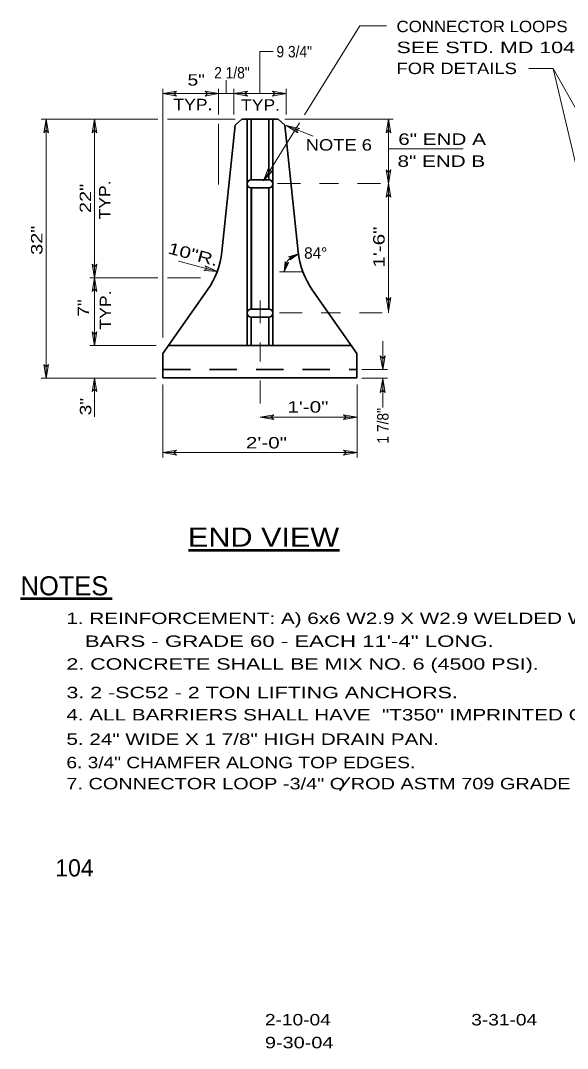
# Model space of a CAD drawing. Extents: x 12.4 to 19.4, y 5.8 to 15.9.
# Drawn here: x 12.38 to 15.25, y 6.26 to 11.65 of the extents above; entities that cross this region are included whole.
import ezdxf
from ezdxf.enums import TextEntityAlignment as Align

# ---------------------------------------------------------------- set-up
doc = ezdxf.new("R2010")
doc.units = 0
doc.header["$LTSCALE"] = 0.024
doc.linetypes.add('DOT_DASHED', pattern=[7.7, 5, -1.2, 0.3, -1.2])
doc.linetypes.add('LONG_DASHED', pattern=[7.5, 6, -1.5])
for name, color, linetype, lineweight in [('1', 7, 'Continuous', 35), ('10', 7, 'Continuous', 13), ('12', 7, 'Continuous', 53), ('13', 7, 'Continuous', 25)]:
    doc.layers.add(name, color=color, linetype=linetype, lineweight=lineweight)

msp = doc.modelspace()

# ---------------------------------------------------------------- hatches: boundary and pattern name
at = {"layer": '10'}
for points in [[(13.1978, 11.2574), (13.1263, 11.27), (13.1978, 11.2826), (13.1843, 11.27)], [(13.3483, 11.2826), (13.4198, 11.27), (13.3483, 11.2574), (13.3618, 11.27)], [(13.5709, 11.2574), (13.4994, 11.27), (13.5709, 11.2826), (13.5574, 11.27)], [(13.7016, 11.2826), (13.7731, 11.27), (13.7016, 11.2574), (13.7151, 11.27)], [(12.5018, 11.0646), (12.5144, 11.1361), (12.527, 11.0646), (12.5144, 11.0781)], [(12.7555, 11.0646), (12.7681, 11.1361), (12.7807, 11.0646), (12.7681, 11.0781)], [(14.2978, 11.0646), (14.3104, 11.1361), (14.323, 11.0646), (14.3104, 11.0781)], [(13.8354, 11.0641), (13.7735, 11.102), (13.8446, 11.0876), (13.8275, 11.0808)], [(13.7032, 10.8665), (13.6547, 10.8125), (13.6818, 10.8799), (13.6853, 10.8617)], [(14.323, 10.8705), (14.3104, 10.799), (14.2978, 10.8705), (14.3104, 10.857)], [(14.2978, 10.7275), (14.3104, 10.799), (14.323, 10.7275), (14.3104, 10.741)], [(13.7861, 10.414), (13.838, 10.4299), (13.7946, 10.3974), (13.7992, 10.4103)], [(12.7807, 10.3749), (12.7681, 10.3034), (12.7555, 10.3749), (12.7681, 10.3614)], [(13.3483, 10.367), (13.4141, 10.3364), (13.3418, 10.3426), (13.3581, 10.3513)], [(13.7873, 10.3848), (13.7641, 10.3355), (13.7691, 10.3898), (13.7757, 10.3773)], [(12.7555, 10.2319), (12.7681, 10.3034), (12.7807, 10.2319), (12.7681, 10.2454)], [(14.323, 10.1997), (14.3104, 10.1282), (14.2978, 10.1997), (14.3104, 10.1862)], [(12.7807, 10.0204), (12.7681, 9.9489), (12.7555, 10.0204), (12.7681, 10.0069)], [(14.2931, 9.894), (14.2805, 9.8225), (14.2679, 9.894), (14.2805, 9.8805)], [(12.527, 9.8494), (12.5144, 9.7779), (12.5018, 9.8494), (12.5144, 9.8359)], [(12.7555, 9.7064), (12.7681, 9.7779), (12.7807, 9.7064), (12.7681, 9.7199)], [(14.2679, 9.7015), (14.2805, 9.773), (14.2931, 9.7015), (14.2805, 9.715)], [(13.7089, 9.5596), (13.6374, 9.5722), (13.7089, 9.5848), (13.6954, 9.5722)], [(14.0747, 9.5848), (14.1462, 9.5722), (14.0747, 9.5596), (14.0882, 9.5722)], [(13.1978, 9.3737), (13.1263, 9.3863), (13.1978, 9.3989), (13.1843, 9.3863)], [(14.0747, 9.3989), (14.1462, 9.3863), (14.0747, 9.3737), (14.0882, 9.3863)]]:
    msp.add_hatch(color=256, dxfattribs=at).paths.add_polyline_path(points)

# ---------------------------------------------------------------- linework, layer by layer
at = {"layer": '1'}
for p, q in [((13.5059, 11.1044), (13.541, 11.1362)), ((13.541, 11.1362), (13.7318, 11.1362)), ((13.569, 11.1357), (13.569, 9.9515)), ((13.5902, 11.1357), (13.5902, 10.8178)), ((13.6832, 11.1357), (13.6832, 10.8178)), ((13.7041, 11.1357), (13.7041, 9.9515)), ((13.7669, 11.1044), (13.7318, 11.1362)), ((13.436, 10.4396), (13.5059, 11.1044)), ((13.8369, 10.4396), (13.7669, 11.1044)), ((13.6832, 10.8178), (13.5902, 10.8178)), ((13.6832, 10.7754), (13.5902, 10.7754)), ((13.6832, 10.7754), (13.6832, 10.1395)), ((13.3616, 10.2409), (13.1277, 9.9068)), ((13.9112, 10.2409), (14.1452, 9.9068)), ((13.6832, 10.1395), (13.5902, 10.1395)), ((13.5902, 9.9515), (13.5902, 10.097)), ((13.6832, 10.097), (13.5902, 10.097)), ((13.6832, 9.9515), (13.6832, 10.097)), ((13.1573, 9.9492), (14.1154, 9.9492)), ((13.1277, 9.7795), (13.1277, 9.9068)), ((14.1452, 9.7795), (14.1452, 9.9068)), ((13.1277, 9.7795), (14.1452, 9.7795))]:
    msp.add_line(p, q, dxfattribs=at)
at = {"layer": '1', "lineweight": 40}
msp.add_line((13.5902, 10.7754), (13.5902, 10.1395), dxfattribs=at)
at = {"layer": '1', "linetype": 'LONG_DASHED'}
msp.add_line((13.1277, 9.8219), (14.1452, 9.8219), dxfattribs=at)
at = {"layer": '1'}
for centre, radius, start, end in [((13.59027, 10.79654), 0.0212, 90.6627, 269.33729), ((13.68293, 10.79654), 0.0212, 270.64822, 89.35178), ((13.0143, 10.48399), 0.42393, 325.00891, 353.98557), ((14.2585, 10.48398), 0.42393, 186.00677, 214.99444), ((13.59027, 10.11825), 0.0212, 90.6627, 269.33729), ((13.68293, 10.11825), 0.0212, 270.64822, 89.35178)]:
    msp.add_arc(centre, radius, start, end, dxfattribs=at)
at = {"layer": '10'}
for p, q in [((14.1612, 11.6264), (13.8708, 11.1596)), ((14.3002, 11.6264), (14.1612, 11.6264)), ((15.1742, 11.4026), (15.471, 10.1432)), ((13.4596, 11.27), (13.4596, 11.3403)), ((13.1263, 9.9911), (13.1263, 11.295)), ((13.1263, 11.27), (13.1978, 11.2826)), ((13.4198, 11.27), (13.3483, 11.2826)), ((13.4198, 11.295), (13.4198, 11.1611)), ((13.4994, 11.1611), (13.4994, 11.295)), ((13.4994, 11.27), (13.5709, 11.2826)), ((13.7731, 11.27), (13.7016, 11.2826)), ((13.7731, 11.1611), (13.7731, 11.295)), ((13.1263, 11.27), (13.1978, 11.2574)), ((13.4198, 11.27), (13.3483, 11.2574)), ((13.4994, 11.27), (13.5709, 11.2574)), ((13.7731, 11.27), (13.7016, 11.2574)), ((12.4894, 11.1361), (13.1013, 11.1361)), ((12.5144, 11.1361), (12.5018, 11.0646)), ((12.5144, 11.1361), (12.5144, 9.7779)), ((12.5144, 11.1361), (12.527, 11.0646)), ((12.7681, 11.1361), (12.7555, 11.0646)), ((12.7681, 11.1361), (12.7681, 10.3034)), ((12.7681, 11.1361), (12.7807, 11.0646)), ((13.506, 11.1361), (13.1513, 11.1361)), ((13.4198, 10.7941), (13.4198, 11.1111)), ((13.6547, 10.8125), (13.8442, 11.1169)), ((13.7668, 11.1361), (14.3354, 11.1361)), ((14.3104, 11.1361), (14.2978, 11.0646)), ((14.3104, 11.1361), (14.323, 11.0646)), ((13.7735, 11.102), (13.9162, 11.0466)), ((13.7735, 11.102), (13.8354, 11.0641)), ((13.7735, 11.102), (13.8446, 11.0876)), ((14.3105, 10.9799), (14.7033, 10.9799)), ((13.6547, 10.8125), (13.6818, 10.8799)), ((13.6547, 10.8125), (13.7032, 10.8665)), ((14.3104, 10.799), (14.2978, 10.8705)), ((14.3104, 10.799), (14.323, 10.8705)), ((14.3104, 10.799), (14.2978, 10.7275)), ((14.3104, 10.799), (14.323, 10.7275)), ((13.838, 10.4299), (13.7861, 10.414)), ((13.838, 10.4299), (13.7946, 10.3974)), ((12.7681, 10.3034), (12.7555, 10.3749)), ((12.7681, 10.3034), (12.7807, 10.3749)), ((13.4141, 10.3364), (13.2099, 10.3908)), ((13.4141, 10.3364), (13.3483, 10.367)), ((13.7641, 10.3355), (13.7691, 10.3898)), ((13.7641, 10.3355), (13.7873, 10.3848)), ((12.7431, 10.3034), (13.1013, 10.3034)), ((12.7681, 10.3034), (12.7555, 10.2319)), ((12.7681, 10.3034), (12.7807, 10.2319)), ((12.7681, 10.3034), (12.7681, 9.9489)), ((13.3253, 10.3034), (13.1513, 10.3034)), ((13.4141, 10.3364), (13.3418, 10.3426)), ((13.8614, 10.3355), (13.7391, 10.3355)), ((14.3104, 10.1282), (14.2978, 10.1997)), ((14.3104, 10.1282), (14.323, 10.1997)), ((12.7681, 9.9489), (12.7555, 10.0204)), ((12.7681, 9.9489), (12.7807, 10.0204)), ((13.0927, 9.9489), (12.7431, 9.9489)), ((14.2805, 9.8225), (14.2805, 9.9716)), ((14.2805, 9.8225), (14.2679, 9.894)), ((14.2805, 9.8225), (14.2931, 9.894)), ((12.5144, 9.7779), (12.5018, 9.8494)), ((12.5144, 9.7779), (12.527, 9.8494)), ((14.1711, 9.8225), (14.3055, 9.8225)), ((13.0927, 9.7779), (12.4894, 9.7779)), ((12.7681, 9.7779), (12.7555, 9.7064)), ((12.7681, 9.7779), (12.7681, 9.5735)), ((12.7681, 9.7779), (12.7807, 9.7064)), ((14.1711, 9.7779), (14.3055, 9.7779)), ((14.2805, 9.773), (14.2679, 9.7015)), ((14.2805, 9.773), (14.2805, 9.6238)), ((14.2805, 9.773), (14.2931, 9.7015)), ((13.1263, 9.7445), (13.1263, 9.3613)), ((14.1462, 9.7445), (14.1462, 9.3613)), ((13.6374, 9.5722), (13.7089, 9.5848)), ((14.1462, 9.5722), (13.6374, 9.5722)), ((13.6374, 9.5722), (13.7089, 9.5596)), ((14.1462, 9.5722), (14.0747, 9.5848)), ((14.1462, 9.5722), (14.0747, 9.5596)), ((13.1263, 9.3863), (13.1978, 9.3989)), ((13.1263, 9.3863), (14.1462, 9.3863)), ((13.1263, 9.3863), (13.1978, 9.3737)), ((14.1462, 9.3863), (14.0747, 9.3989)), ((14.1462, 9.3863), (14.0747, 9.3737))]:
    msp.add_line(p, q, dxfattribs=at)
at = {"layer": '10', "linetype": 'DOT_DASHED'}
for p, q in [((13.7283, 10.799), (14.3354, 10.799)), ((13.6374, 10.1849), (13.6374, 9.5472)), ((13.7382, 10.1199), (14.3354, 10.1199))]:
    msp.add_line(p, q, dxfattribs=at)
at = {"layer": '10'}
for points in [[(13.6363, 11.27), (13.6363, 11.4919), (13.7066, 11.4919)], [(15.0476, 11.4026), (15.1742, 11.4026), (15.5051, 10.8165)], [(13.1978, 11.2574), (13.1843, 11.27), (13.1978, 11.2826)], [(13.3483, 11.2826), (13.3618, 11.27), (13.3483, 11.2574)], [(13.5709, 11.2574), (13.5574, 11.27), (13.5709, 11.2826)], [(13.7016, 11.2826), (13.7151, 11.27), (13.7016, 11.2574)], [(13.1263, 11.27), (13.4198, 11.27), (13.4994, 11.27), (13.7731, 11.27)], [(14.3104, 11.1361), (14.3104, 10.799), (14.3104, 10.1199)], [(12.5018, 11.0646), (12.5144, 11.0781), (12.527, 11.0646)], [(12.7555, 11.0646), (12.7681, 11.0781), (12.7807, 11.0646)], [(13.8354, 11.0641), (13.8275, 11.0808), (13.8446, 11.0876)], [(14.2978, 11.0646), (14.3104, 11.0781), (14.323, 11.0646)], [(13.7032, 10.8665), (13.6853, 10.8617), (13.6818, 10.8799)], [(14.323, 10.8705), (14.3104, 10.857), (14.2978, 10.8705)], [(14.2978, 10.7275), (14.3104, 10.741), (14.323, 10.7275)], [(13.7861, 10.414), (13.7992, 10.4103), (13.7946, 10.3974)], [(12.7807, 10.3749), (12.7681, 10.3614), (12.7555, 10.3749)], [(13.3483, 10.367), (13.3581, 10.3513), (13.3418, 10.3426)], [(13.7873, 10.3848), (13.7757, 10.3773), (13.7691, 10.3898)], [(12.7555, 10.2319), (12.7681, 10.2454), (12.7807, 10.2319)], [(14.323, 10.1997), (14.3104, 10.1862), (14.2978, 10.1997)], [(12.7807, 10.0204), (12.7681, 10.0069), (12.7555, 10.0204)], [(14.2931, 9.894), (14.2805, 9.8805), (14.2679, 9.894)], [(12.527, 9.8494), (12.5144, 9.8359), (12.5018, 9.8494)], [(12.7555, 9.7064), (12.7681, 9.7199), (12.7807, 9.7064)], [(14.2679, 9.7015), (14.2805, 9.715), (14.2931, 9.7015)], [(13.7089, 9.5596), (13.6954, 9.5722), (13.7089, 9.5848)], [(14.0747, 9.5848), (14.0882, 9.5722), (14.0747, 9.5596)], [(13.1978, 9.3737), (13.1843, 9.3863), (13.1978, 9.3989)], [(14.0747, 9.3989), (14.0882, 9.3863), (14.0747, 9.3737)]]:
    msp.add_lwpolyline(points, dxfattribs=at)
for points in [[(13.1978, 11.2574), (13.1263, 11.27), (13.1978, 11.2826), (13.1843, 11.27)], [(13.3483, 11.2826), (13.4198, 11.27), (13.3483, 11.2574), (13.3618, 11.27)], [(13.5709, 11.2574), (13.4994, 11.27), (13.5709, 11.2826), (13.5574, 11.27)], [(13.7016, 11.2826), (13.7731, 11.27), (13.7016, 11.2574), (13.7151, 11.27)], [(12.5018, 11.0646), (12.5144, 11.1361), (12.527, 11.0646), (12.5144, 11.0781)], [(12.7555, 11.0646), (12.7681, 11.1361), (12.7807, 11.0646), (12.7681, 11.0781)], [(14.2978, 11.0646), (14.3104, 11.1361), (14.323, 11.0646), (14.3104, 11.0781)], [(13.8354, 11.0641), (13.7735, 11.102), (13.8446, 11.0876), (13.8275, 11.0808)], [(13.7032, 10.8665), (13.6547, 10.8125), (13.6818, 10.8799), (13.6853, 10.8617)], [(14.323, 10.8705), (14.3104, 10.799), (14.2978, 10.8705), (14.3104, 10.857)], [(14.2978, 10.7275), (14.3104, 10.799), (14.323, 10.7275), (14.3104, 10.741)], [(13.7861, 10.414), (13.838, 10.4299), (13.7946, 10.3974), (13.7992, 10.4103)], [(12.7807, 10.3749), (12.7681, 10.3034), (12.7555, 10.3749), (12.7681, 10.3614)], [(13.3483, 10.367), (13.4141, 10.3364), (13.3418, 10.3426), (13.3581, 10.3513)], [(13.7873, 10.3848), (13.7641, 10.3355), (13.7691, 10.3898), (13.7757, 10.3773)], [(12.7555, 10.2319), (12.7681, 10.3034), (12.7807, 10.2319), (12.7681, 10.2454)], [(14.323, 10.1997), (14.3104, 10.1282), (14.2978, 10.1997), (14.3104, 10.1862)], [(12.7807, 10.0204), (12.7681, 9.9489), (12.7555, 10.0204), (12.7681, 10.0069)], [(14.2931, 9.894), (14.2805, 9.8225), (14.2679, 9.894), (14.2805, 9.8805)], [(12.527, 9.8494), (12.5144, 9.7779), (12.5018, 9.8494), (12.5144, 9.8359)], [(12.7555, 9.7064), (12.7681, 9.7779), (12.7807, 9.7064), (12.7681, 9.7199)], [(14.2679, 9.7015), (14.2805, 9.773), (14.2931, 9.7015), (14.2805, 9.715)], [(13.7089, 9.5596), (13.6374, 9.5722), (13.7089, 9.5848), (13.6954, 9.5722)], [(14.0747, 9.5848), (14.1462, 9.5722), (14.0747, 9.5596), (14.0882, 9.5722)], [(13.1978, 9.3737), (13.1263, 9.3863), (13.1978, 9.3989), (13.1843, 9.3863)], [(14.0747, 9.3989), (14.1462, 9.3863), (14.0747, 9.3737), (14.0882, 9.3863)]]:
    msp.add_lwpolyline(points, close=True, dxfattribs=at)
msp.add_arc((13.86144, 10.33551), 0.0973, 103.92901, 180, dxfattribs=at)
at = {"layer": '12'}
msp.add_line((13.2624, 8.8746), (14.0546, 8.8746), dxfattribs=at)
at = {"layer": '13', "lineweight": 53}
msp.add_line((12.3805, 8.6209), (12.8615, 8.6209), dxfattribs=at)
at = {"layer": '13'}
msp.add_line((14.1065, 7.6846), (14.0539, 7.6115), dxfattribs=at)

# ---------------------------------------------------------------- texts
at = {"layer": '12'}
for s, width, p in [('CONNECTOR LOOPS', 1.1, (14.353, 11.5925)), ('SEE STD. MD 104.01-54', 1.4, (14.353, 11.4825)), ('9 3/4"', 0.9, (13.7232, 11.4604)), ('FOR DETAILS', 1.2, (14.353, 11.3725)), ('2 1/8"', 0.9, (13.3964, 11.3496)), ('5"', 1.25, (13.2565, 11.3118)), ('TYP.', 1.15, (13.1821, 11.1828)), ('TYP.', 1.15, (13.5368, 11.1806)), ('6" END A', 1.35, (14.362, 11.0011)), ('NOTE 6', 1.2, (13.8763, 10.9711)), ('8" END B', 1.35, (14.3582, 10.8858)), ('1\'-0"', 1.35, (13.7802, 9.5963)), ('2\'-0"', 1.35, (13.5627, 9.4083))]:
    msp.add_text(s, height=0.06, dxfattribs=dict(at, width=width)).set_placement(p)
for s, rotation, width, p in [('22"', 90, 1.3, (12.7506, 10.6438)), ('TYP.', 90, 1.15, (12.8522, 10.6098)), ('32"', 90, 1.3, (12.4953, 10.4241)), ('1\'-6"', 90, 1.35, (14.2905, 10.357)), ('10"R.', 345.076, 1.35, (13.1495, 10.4327)), ('TYP.', 90, 1.15, (12.8557, 10.0319)), ('7"', 90, 1.25, (12.7398, 10.0996)), ('3"', 90, 1.25, (12.7515, 9.5821)), ('1 7/8"', 90, 0.9, (14.3112, 9.4341))]:
    msp.add_text(s, height=0.06, rotation=rotation, dxfattribs=dict(at, width=width)).set_placement(p)
msp.add_text('84°', height=0.06, dxfattribs=at).set_placement((13.8681, 10.4037))
at = {"layer": '12', "width": 1.2}
msp.add_text('END VIEW', height=0.1, dxfattribs=at).set_placement((13.6555, 8.8932), align=Align.CENTER)
at = {"layer": '13'}
msp.add_text('NOTES', height=0.1, dxfattribs=at).set_placement((12.3805, 8.6378))
for s, width, p in [('1. REINFORCEMENT: A) 6x6 W2.9 X W2.9 WELDED WIRE FABRIC FOLDED IN U SHAPE. B) 2- NO.4 1/2" 0 REINFORCEMENT', 1.35, (12.621, 8.4872)), ('   BARS - GRADE 60 - EACH 11\'-4" LONG.', 1.45, (12.621, 8.3672)), ('2. CONCRETE SHALL BE MIX NO. 6 (4500 PSI).', 1.4, (12.621, 8.2476)), ('3. 2 -SC52 - 2 TON LIFTING ANCHORS.', 1.4, (12.621, 8.0978)), ('4. ALL BARRIERS SHALL HAVE  "T350" IMPRINTED ON TOP END OF BARRIER.', 1.35, (12.621, 7.9812)), ('5. 24" WIDE X 1 7/8" HIGH DRAIN PAN.', 1.35, (12.621, 7.853)), ('6. 3/4" CHAMFER ALONG TOP EDGES.', 1.25, (12.621, 7.7306)), ('7. CONNECTOR LOOP -3/4" O ROD ASTM 709 GRADE 36 PLAIN SHALL CONFORM TO ASTM A 153.', 1.3, (12.621, 7.6198)), ('2-10-04', 1.25, (13.6625, 6.3813)), ('3-31-04', 1.25, (14.7449, 6.3813)), ('9-30-04', 1.3, (13.6625, 6.2613))]:
    msp.add_text(s, height=0.06, dxfattribs=dict(at, width=width)).set_placement(p)
msp.add_text('104', height=0.09, dxfattribs=at).set_placement((12.6632, 7.1629), align=Align.CENTER)

doc.saveas('drawing.dxf')
